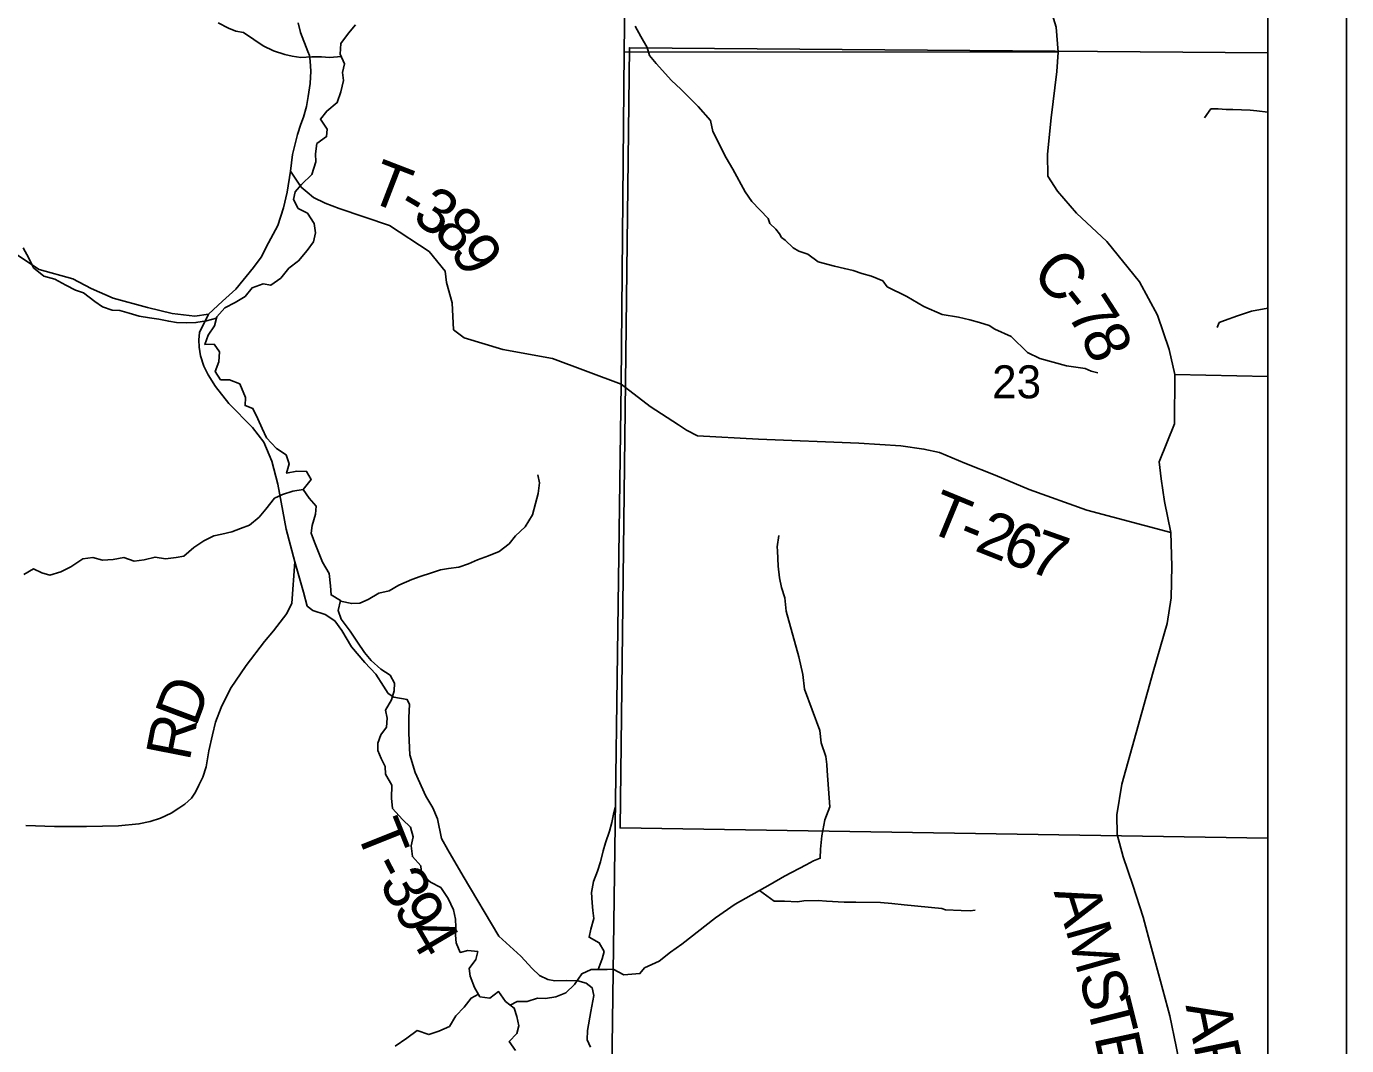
# Model space of a CAD drawing. Extents: x -20.5 to 34, y -66 to 23.9.
# Drawn here: x 7.323 to 9, y 15.05 to 16.344 of the extents above; entities that cross this region are included whole.
import ezdxf

# ---------------------------------------------------------------- set-up
doc = ezdxf.new("R2010")
doc.units = 0
for name, color, linetype in [('Default', 7, 'Continuous'), ('GM_X_County_Text', 7, 'Continuous'), ('GM_X_Minor_River_Text', 7, 'Continuous'), ('GM_X_Section_Text', 7, 'Continuous'), ('GM_X_State_Route', 7, 'Continuous'), ('GM_X_Township_Road_Text', 7, 'Continuous'), ('GM_X_Township_Text', 7, 'Continuous'), ('SH_Cut_Line', 7, 'Continuous'), ('SH_Data', 7, 'Continuous')]:
    doc.layers.add(name, color=color, linetype=linetype)

msp = doc.modelspace()

# ---------------------------------------------------------------- linework, layer by layer
at = {"layer": 'Default'}
for points in [[(2.1, 20.9), (8.9, 20.9), (8.9, 14.1), (2.1, 14.1)], [(8.9, 14.3068), (8.9, 17.3115), (8.5216, 17.3182), (8.271, 17.3227), (8.2289, 17.3235), (8.0955, 17.3258), (8.087, 16.6605), (8.0825, 16.3121), (8.0784, 15.8902), (8.0662, 14.9881), (8.0605, 14.6038), (8.0589, 14.5033), (8.0585, 14.4588), (8.0565, 14.3169), (8.8167, 14.3089)], [(8.9, 15.3136), (8.9, 16.3104), (8.089, 16.3168), (8.0772, 15.3265)]]:
    msp.add_lwpolyline(points, close=True, dxfattribs=at)
msp.add_lwpolyline([(8.0662, 14.9881), (8.0784, 15.8902), (8.0825, 16.3121), (8.087, 16.6605), (8.0955, 17.3258), (8.2289, 17.3235), (8.271, 17.3227), (8.5216, 17.3182), (8.9, 17.3115), (8.9, 18.8361), (8.7292, 18.8379), (8.3774, 18.8452)], dxfattribs=at)
at = {"layer": 'GM_X_County_Text'}
for p, q in [((8.0827, 16.3115), (8.6336, 16.3114)), ((8.7819, 15.9019), (8.9, 15.8995))]:
    msp.add_line(p, q, dxfattribs=at)
for points in [[(7.5544, 15.9786), (7.5723, 15.9953), (7.589, 16.0106), (7.6117, 16.0379), (7.6213, 16.051), (7.6307, 16.0692), (7.6422, 16.0913), (7.6496, 16.1136), (7.6542, 16.1336), (7.6587, 16.1602)], [(7.6587, 16.1602), (7.6721, 16.14), (7.6797, 16.1335), (7.6877, 16.1266), (7.7027, 16.1196), (7.7204, 16.1128), (7.7844, 16.0912), (7.8346, 16.0581), (7.855, 16.0333), (7.8565, 16.0188), (7.8639, 15.9931), (7.8655, 15.9589), (7.879, 15.9486), (7.9281, 15.9337), (7.9915, 15.9222), (8.0786, 15.8897)], [(7.0921, 16.1083), (7.1009, 16.1099), (7.1608, 16.1192), (7.1882, 16.1179), (7.2219, 16.1084), (7.2565, 16.0928), (7.2963, 16.0637), (7.3392, 16.0353), (7.382, 16.0234), (7.4052, 16.0112), (7.4333, 15.999), (7.4767, 15.9871), (7.5082, 15.9797), (7.5368, 15.9763), (7.5544, 15.9786)], [(8.7768, 15.7016), (8.7688, 15.7409), (8.7645, 15.7697), (8.7621, 15.7913), (8.7813, 15.8395), (8.7819, 15.9019)], [(8.0786, 15.8897), (8.1153, 15.8613), (8.1514, 15.8381), (8.1614, 15.8315), (8.1755, 15.8241), (8.2529, 15.82), (8.3806, 15.8149), (8.4337, 15.8114), (8.463, 15.8074), (8.4828, 15.8029), (8.5152, 15.7894), (8.5534, 15.7743), (8.5969, 15.7561), (8.6702, 15.7298), (8.7768, 15.7016)], [(8.0394, 15.0484), (8.0354, 15.0576), (8.0359, 15.0692), (8.04, 15.0934), (8.044, 15.1136), (8.0415, 15.1236), (8.034, 15.1296), (8.0236, 15.1325), (8.0096, 15.133), (7.9944, 15.1323), (7.9855, 15.134), (7.9747, 15.139), (7.9655, 15.1481), (7.9512, 15.1637), (7.9231, 15.189), (7.8779, 15.2651), (7.8583, 15.2986), (7.8501, 15.3132), (7.8451, 15.3381), (7.8391, 15.3519), (7.8306, 15.3669), (7.817, 15.3968), (7.8099, 15.4195), (7.8089, 15.4468), (7.809, 15.4667), (7.8096, 15.483), (7.8067, 15.4894), (7.7896, 15.4926), (7.7825, 15.4973), (7.7768, 15.5065), (7.7669, 15.5215), (7.753, 15.5364), (7.7359, 15.5563), (7.7235, 15.5771), (7.7148, 15.5894), (7.7025, 15.5976), (7.6868, 15.6024), (7.6795, 15.6081), (7.6752, 15.6259), (7.664, 15.6642)]]:
    msp.add_lwpolyline(points, dxfattribs=at)
at = {"layer": 'GM_X_Minor_River_Text'}
for points in [[(7.7412, 16.3459), (7.7323, 16.3352), (7.7223, 16.3221), (7.7217, 16.3088), (7.7272, 16.2964), (7.7247, 16.2854), (7.726, 16.2751), (7.7224, 16.261), (7.7177, 16.2473), (7.7046, 16.2365), (7.6965, 16.2261), (7.705, 16.2137), (7.7044, 16.2042), (7.692, 16.1953), (7.6903, 16.1824), (7.6908, 16.1721), (7.6854, 16.1561), (7.6724, 16.1434), (7.6645, 16.1338), (7.6624, 16.1243), (7.6683, 16.113), (7.6801, 16.1067), (7.6886, 16.0939), (7.6903, 16.0818), (7.6878, 16.0707), (7.6797, 16.0596), (7.6685, 16.0465), (7.6562, 16.0369), (7.6461, 16.0242), (7.6334, 16.0153), (7.6239, 16.017), (7.6096, 16.0123), (7.6007, 16.0011), (7.5883, 15.9937), (7.5752, 15.9867), (7.5651, 15.9755), (7.5619, 15.9637), (7.5541, 15.9522), (7.5498, 15.94), (7.5615, 15.9406), (7.5684, 15.9308), (7.5675, 15.9183), (7.5628, 15.906), (7.5697, 15.8955), (7.5811, 15.8953), (7.594, 15.8902), (7.6015, 15.8728), (7.6009, 15.8626), (7.6108, 15.8589), (7.617, 15.8457), (7.6225, 15.8337), (7.628, 15.8216), (7.6406, 15.8081), (7.6529, 15.8), (7.6568, 15.7886), (7.6536, 15.7768), (7.6664, 15.7793), (7.6789, 15.7791), (7.6847, 15.7689), (7.6747, 15.7563), (7.6824, 15.745), (7.6909, 15.7349)], [(7.7231, 16.3057), (7.7082, 16.3045), (7.6979, 16.3055), (7.6854, 16.3053), (7.6718, 16.3043), (7.6608, 16.306), (7.6513, 16.3082), (7.6369, 16.3129), (7.6239, 16.3191), (7.6121, 16.3273), (7.5987, 16.3362), (7.5892, 16.338), (7.5797, 16.3416), (7.5667, 16.3483)], [(8.0961, 16.3444), (8.1036, 16.3313), (8.1114, 16.317), (8.1147, 16.3072), (8.1229, 16.2968), (8.1423, 16.2752), (8.1542, 16.2644), (8.1763, 16.2425), (8.1922, 16.2246), (8.1948, 16.2106), (8.2118, 16.1772), (8.2204, 16.1629), (8.2362, 16.134), (8.2444, 16.1217), (8.2653, 16.1001), (8.2673, 16.0937), (8.2751, 16.0867), (8.2797, 16.0807), (8.2821, 16.0762), (8.2867, 16.0725), (8.2972, 16.0628), (8.3041, 16.0588), (8.3156, 16.0549), (8.3286, 16.0453), (8.3493, 16.0396), (8.3622, 16.0365), (8.3733, 16.0341), (8.3844, 16.0305), (8.3966, 16.027), (8.4108, 16.0208), (8.4166, 16.0134), (8.4412, 16.001), (8.4631, 15.9886), (8.4864, 15.9784), (8.507, 15.9747), (8.5215, 15.9716), (8.5337, 15.968), (8.5459, 15.9641), (8.5532, 15.9597), (8.5739, 15.9503), (8.5948, 15.9299), (8.6105, 15.9226), (8.6441, 15.9131), (8.6678, 15.9098), (8.6754, 15.9065), (8.6838, 15.9044)], [(8.9, 16.2353), (8.8859, 16.2368), (8.8775, 16.2378), (8.8554, 16.2385), (8.8471, 16.2387), (8.8368, 16.2392), (8.8277, 16.2394), (8.8196, 16.2278)], [(7.5646, 15.9737), (7.5516, 15.9704), (7.5384, 15.9679), (7.5263, 15.9677), (7.5138, 15.9683), (7.5039, 15.9697), (7.4914, 15.9722), (7.4793, 15.9742), (7.4664, 15.9763), (7.4534, 15.9799), (7.4417, 15.9832), (7.4318, 15.9838), (7.4196, 15.9882), (7.4101, 15.9948), (7.3955, 16.0056), (7.3853, 16.0093), (7.3731, 16.0156), (7.359, 16.0233), (7.3453, 16.0269), (7.3319, 16.0377), (7.326, 16.0498), (7.319, 16.0629)], [(8.9, 15.9865), (8.8794, 15.9827), (8.8613, 15.9766), (8.8447, 15.9706), (8.8383, 15.9681), (8.8354, 15.9616)], [(7.7219, 15.6142), (7.7363, 15.6114), (7.7465, 15.6119), (7.757, 15.6163), (7.7705, 15.6244), (7.7837, 15.6273), (7.7961, 15.6347), (7.8126, 15.6418), (7.8232, 15.6457), (7.8375, 15.6505), (7.8491, 15.6541), (7.859, 15.6558), (7.8722, 15.6575), (7.8846, 15.6618), (7.8959, 15.6669), (7.9098, 15.6721), (7.9237, 15.6776), (7.9361, 15.6873), (7.9442, 15.6973), (7.9566, 15.7089), (7.9658, 15.7238), (7.9697, 15.7383), (7.9733, 15.7512), (7.9746, 15.7646), (7.9726, 15.7748)], [(7.6747, 15.7563), (7.6615, 15.7542), (7.6483, 15.7498), (7.6382, 15.7451), (7.627, 15.7312), (7.6185, 15.7212), (7.6065, 15.7108), (7.5949, 15.7065), (7.5839, 15.7025), (7.5711, 15.6993), (7.5609, 15.6972), (7.5485, 15.691), (7.5358, 15.6824), (7.5231, 15.6716), (7.5133, 15.6699), (7.4997, 15.6682), (7.4864, 15.6703), (7.4725, 15.667), (7.46, 15.665), (7.4467, 15.6697), (7.4331, 15.6672), (7.4195, 15.6666), (7.4073, 15.6699), (7.3945, 15.6681), (7.3795, 15.658), (7.3667, 15.6514), (7.3528, 15.6474), (7.3425, 15.6503), (7.3319, 15.6554), (7.3199, 15.6484)], [(7.6909, 15.7349), (7.6903, 15.725), (7.686, 15.7105), (7.6846, 15.7006), (7.6889, 15.6893), (7.6941, 15.6764), (7.6992, 15.664), (7.7077, 15.6497), (7.7091, 15.6338), (7.71, 15.6224), (7.7222, 15.6154), (7.719, 15.6024), (7.7229, 15.5915), (7.7341, 15.5764), (7.7438, 15.5625), (7.7527, 15.5494), (7.7608, 15.5389), (7.7734, 15.5281), (7.7849, 15.5203), (7.7904, 15.5101), (7.7901, 15.5006), (7.7869, 15.4891), (7.7791, 15.4761), (7.7812, 15.4659), (7.7806, 15.4545), (7.7732, 15.4449), (7.7695, 15.4342), (7.7693, 15.4247), (7.7736, 15.4145), (7.7787, 15.4044), (7.7792, 15.3949), (7.7873, 15.381), (7.7868, 15.3642), (7.7882, 15.351), (7.8009, 15.3371), (7.8108, 15.3274), (7.8144, 15.3153), (7.8116, 15.3039), (7.8133, 15.2902), (7.824, 15.2786), (7.825, 15.2672), (7.8365, 15.2575), (7.8494, 15.2509), (7.8587, 15.237), (7.8657, 15.2227), (7.8682, 15.2106), (7.8683, 15.2007), (7.8681, 15.1904), (7.869, 15.1806), (7.8741, 15.1685), (7.8839, 15.1709), (7.8964, 15.1696), (7.8939, 15.1597), (7.8854, 15.1482), (7.8867, 15.1383), (7.8922, 15.124), (7.8991, 15.1123), (7.9117, 15.1106), (7.9229, 15.1187), (7.9318, 15.106), (7.9425, 15.0978), (7.9461, 15.0872), (7.9485, 15.0751), (7.946, 15.0656), (7.9363, 15.0552), (7.9441, 15.0439)], [(8.3401, 15.3991), (8.3399, 15.4072), (8.3385, 15.417), (8.3325, 15.4347), (8.3307, 15.4503), (8.3114, 15.5027), (8.3092, 15.5212), (8.3042, 15.5439), (8.2882, 15.6017), (8.2864, 15.6187), (8.282, 15.6319), (8.2795, 15.644), (8.278, 15.6588), (8.2769, 15.6781), (8.2768, 15.6834), (8.2788, 15.6979)], [(8.0684, 15.1473), (8.082, 15.1399), (8.1023, 15.1416), (8.1082, 15.1489), (8.1267, 15.1573), (8.1413, 15.1686), (8.1555, 15.1788), (8.1982, 15.2124), (8.2233, 15.2296), (8.2676, 15.2549), (8.286, 15.2651), (8.3134, 15.2798), (8.3228, 15.2849), (8.3315, 15.2881), (8.3317, 15.2995), (8.3336, 15.3163), (8.3374, 15.3369), (8.3435, 15.3533), (8.3401, 15.3991)], [(8.0492, 15.1468), (8.0543, 15.1602), (8.0569, 15.1697), (8.0506, 15.1807), (8.0377, 15.1877), (8.0398, 15.198), (8.0437, 15.2117), (8.0425, 15.2215), (8.0416, 15.2314), (8.041, 15.2447), (8.0434, 15.2584), (8.0485, 15.2717), (8.0521, 15.2836), (8.0557, 15.2973), (8.0586, 15.3076), (8.0637, 15.3225), (8.0665, 15.3335), (8.069, 15.3461), (8.0711, 15.3527)], [(8.2541, 15.2472), (8.2729, 15.2337), (8.2859, 15.2336), (8.3026, 15.2328), (8.3105, 15.2338), (8.3287, 15.2345), (8.3394, 15.2336), (8.3618, 15.2322), (8.3766, 15.2321), (8.4078, 15.232), (8.4223, 15.2305), (8.4382, 15.2289), (8.4858, 15.2242), (8.4904, 15.2224), (8.5105, 15.2217), (8.5219, 15.2212), (8.5284, 15.2221)], [(7.9374, 15.1017), (7.9465, 15.1062), (7.959, 15.106), (7.9722, 15.1104), (7.9824, 15.1098), (7.9956, 15.1122), (8.0084, 15.117), (8.0193, 15.1278), (8.0285, 15.1412), (8.0405, 15.1467), (8.0508, 15.1469), (8.0606, 15.1466), (8.0684, 15.1473)], [(7.8972, 15.1156), (7.8878, 15.1106), (7.8789, 15.0991), (7.8685, 15.0879), (7.8604, 15.0745), (7.8468, 15.0686), (7.834, 15.0642), (7.8196, 15.0693), (7.8061, 15.0596), (7.7915, 15.0496)]]:
    msp.add_lwpolyline(points, dxfattribs=at)
at = {"layer": 'GM_X_State_Route'}
for points in [[(8.7819, 15.9019), (8.7748, 15.934), (8.7596, 15.9774), (8.7368, 16.0198), (8.6956, 16.0711), (8.657, 16.1068), (8.6326, 16.1348), (8.6205, 16.1539), (8.6199, 16.182), (8.6247, 16.228), (8.6319, 16.2867), (8.6336, 16.3114), (8.6311, 16.3432), (8.6177, 16.3874)], [(7.6682, 16.3487), (7.6714, 16.3363), (7.6804, 16.3122), (7.6825, 16.307), (7.6834, 16.3), (7.6843, 16.2872), (7.6834, 16.2715), (7.681, 16.2549), (7.6787, 16.2422), (7.6749, 16.2286), (7.6718, 16.2199), (7.6673, 16.2069), (7.6638, 16.1931), (7.6609, 16.1814), (7.6587, 16.1602)], [(7.6587, 16.1602), (7.6542, 16.1336), (7.6496, 16.1136), (7.6422, 16.0913), (7.6307, 16.0692), (7.6213, 16.051), (7.6117, 16.0379), (7.589, 16.0106), (7.5723, 15.9953), (7.5544, 15.9786)], [(7.5544, 15.9786), (7.5427, 15.9556), (7.5421, 15.9461), (7.5425, 15.9367), (7.5442, 15.9257), (7.5486, 15.9125), (7.5537, 15.9017), (7.5634, 15.8869), (7.5801, 15.8651), (7.6102, 15.835), (7.6246, 15.8163), (7.6346, 15.7919), (7.6426, 15.7631), (7.6531, 15.7057), (7.664, 15.6642), (7.6601, 15.6119), (7.6537, 15.5987), (7.6371, 15.5766), (7.6256, 15.5633), (7.6022, 15.5325), (7.5822, 15.5036), (7.5703, 15.4795), (7.5632, 15.4608), (7.5595, 15.4447), (7.5549, 15.4242), (7.5514, 15.4039), (7.5471, 15.391), (7.542, 15.3807), (7.538, 15.3721), (7.5327, 15.3644), (7.5242, 15.3566), (7.5167, 15.3514), (7.5067, 15.3453), (7.4932, 15.3389), (7.4802, 15.3347), (7.4659, 15.3317), (7.4402, 15.3292), (7.3995, 15.3282), (7.3589, 15.3285), (7.3223, 15.3297)], [(8.7768, 15.7016), (8.7688, 15.7409), (8.7645, 15.7697), (8.7621, 15.7913), (8.7813, 15.8395), (8.7819, 15.9019)], [(8.9, 14.8489), (8.8806, 14.8723), (8.853, 14.9105), (8.8359, 14.9322), (8.8153, 14.9569), (8.7989, 14.9809), (8.7945, 14.9941), (8.7836, 15.049), (8.7753, 15.0879), (8.7638, 15.1318), (8.7483, 15.1877), (8.7417, 15.2134), (8.7284, 15.2538), (8.716, 15.29), (8.7086, 15.318), (8.7081, 15.3431), (8.7145, 15.382), (8.7326, 15.4473), (8.7541, 15.5248), (8.7719, 15.586), (8.7773, 15.6184), (8.778, 15.659), (8.7768, 15.7016)]]:
    msp.add_lwpolyline(points, dxfattribs=at)
at = {"layer": 'SH_Cut_Line'}
msp.add_lwpolyline([(8.0662, 14.9881), (8.0784, 15.8902), (8.0825, 16.3121), (8.087, 16.6605), (8.0955, 17.3258), (8.2289, 17.3235), (8.271, 17.3227), (8.5216, 17.3182), (8.9, 17.3115), (8.9, 20.9), (2.1, 20.9), (2.1, 14.4131)], dxfattribs=at)
msp.add_lwpolyline([(8.9, 14.3068), (8.9, 17.3115), (8.5216, 17.3182), (8.271, 17.3227), (8.2289, 17.3235), (8.0955, 17.3258), (8.087, 16.6605), (8.0825, 16.3121), (8.0784, 15.8902), (8.0662, 14.9881), (8.0605, 14.6038), (8.0589, 14.5033), (8.0585, 14.4588), (8.0565, 14.3169), (8.8167, 14.3089)], close=True, dxfattribs=at)
at = {"layer": 'SH_Data'}
for p, q in [((9, 21), (9, 14)), ((8.9, 20.9), (8.9, 14.1))]:
    msp.add_line(p, q, dxfattribs=at)

# ---------------------------------------------------------------- texts
at = {"layer": 'GM_X_Section_Text'}
for s, rotation, p in [('T', 338.9214, (7.7546, 16.1233)), ('3', 326.2183, (7.8111, 16.0978)), ('-', 329.4678, (7.7919, 16.1091)), ('8', 316.5454, (7.838, 16.0801)), ('9', 299.4237, (7.8605, 16.0597)), ('T', 337.6177, (8.4642, 15.7044)), ('2', 338.4969, (8.526, 15.6791)), ('6', 339.4488, (8.5595, 15.6659)), ('-', 337.8576, (8.5037, 15.6881)), ('7', 340.5404, (8.5934, 15.6532)), ('T', 291.8094, (7.7408, 15.3237)), ('-', 297.3248, (7.7591, 15.2788)), ('3', 298.6751, (7.7704, 15.2568)), ('9', 300.084, (7.788, 15.2247)), ('4', 300.4555, (7.8057, 15.1941))]:
    msp.add_text(s, height=0.0568, rotation=rotation, dxfattribs=at).set_placement(p)
at = {"layer": 'GM_X_Township_Road_Text'}
for s, rotation, p in [('C', 315.0359, (8.5978, 16.0275)), ('-', 308.5781, (8.6297, 15.9957)), ('7', 302.8428, (8.6434, 15.9787)), ('8', 294.2021, (8.6613, 15.9513)), ('D', 69.4853, (7.5384, 15.4535)), ('R', 78.8573, (7.5301, 15.4101)), ('A', 287.499, (8.6277, 15.2455)), ('M', 285.7486, (8.6426, 15.1983)), ('S', 284.9144, (8.6593, 15.1391)), ('T', 284.0539, (8.6691, 15.1023)), ('A', 281.5007, (8.7953, 15.1011)), ('E', 282.0538, (8.6793, 15.0616)), ('P', 281.6128, (8.8053, 15.052))]:
    msp.add_text(s, height=0.0568, rotation=rotation, dxfattribs=at).set_placement(p)
at = {"layer": 'GM_X_Township_Text'}
msp.add_text('23', height=0.04186, rotation=0, dxfattribs=at).set_placement((8.5497, 15.8719))

doc.saveas('drawing.dxf')
